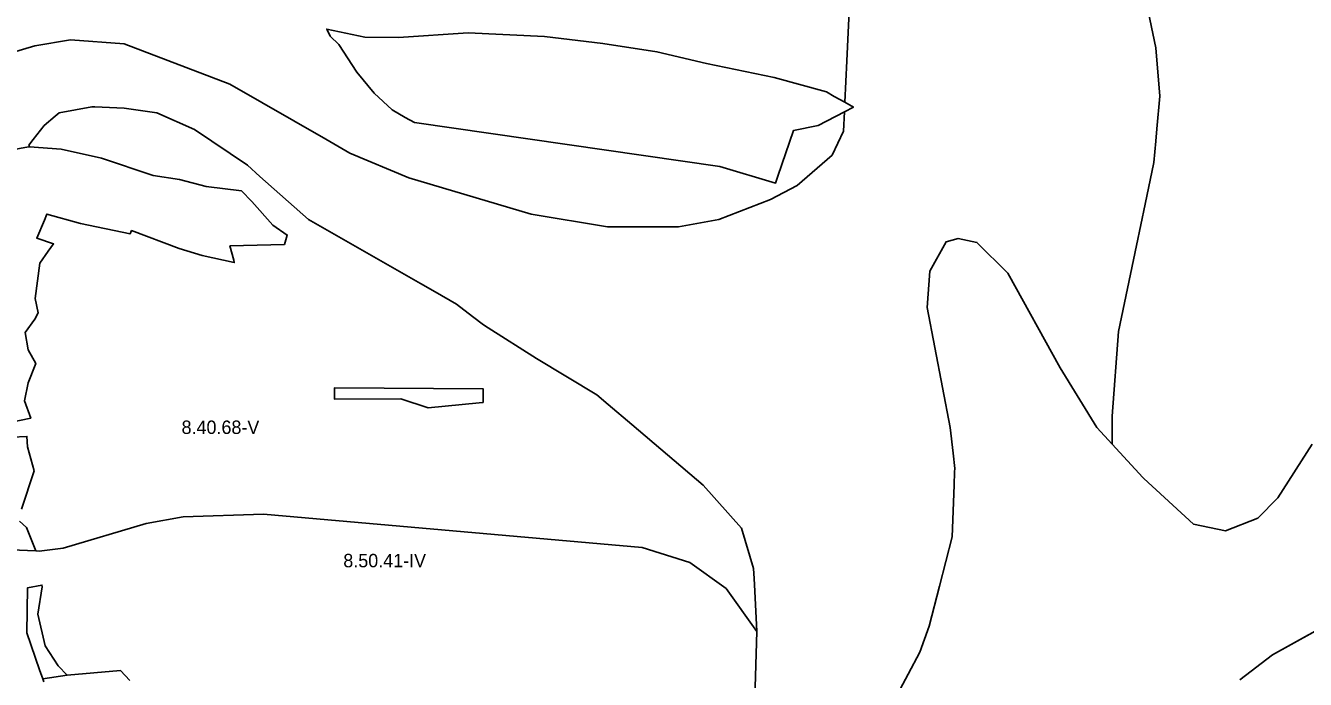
# Model space of a CAD drawing. Extents: x -547623 to -533936, y -1096714 to -1086523.
# Drawn here: x -543738 to -542784, y -1092854 to -1092367 of the extents above; entities that cross this region are included whole.
import ezdxf

# ---------------------------------------------------------------- set-up
doc = ezdxf.new("R2010")
doc.units = 0
doc.layers.add('Vrstva 27', color=7, linetype='Continuous')
doc.layers.add('Vrstva 28', color=7, linetype='Continuous')

msp = doc.modelspace()

# ---------------------------------------------------------------- linework, layer by layer
at = {"layer": 'Vrstva 28'}
for p, q in [((-542905, -1092338.5), (-542895.5, -1092383.5)), ((-542895.5, -1092383.5), (-542905, -1092338.5)), ((-543126.01, -1092393.13), (-543124, -1092351)), ((-543124, -1092351), (-543126.01, -1092393.13)), ((-543750, -1092387.4), (-543731.5, -1092382)), ((-543731.5, -1092382), (-543750, -1092387.4)), ((-543731.5, -1092382), (-543705, -1092377.5)), ((-543705, -1092377.5), (-543731.5, -1092382)), ((-543705, -1092377.5), (-543665, -1092380.5)), ((-543665, -1092380.5), (-543705, -1092377.5)), ((-543665, -1092380.5), (-543586, -1092410.5)), ((-543586, -1092410.5), (-543665, -1092380.5)), ((-542895.5, -1092383.5), (-542892.5, -1092419.5)), ((-542892.5, -1092419.5), (-542895.5, -1092383.5)), ((-543127.48, -1092424.11), (-543126.01, -1092393.13)), ((-543126.01, -1092393.13), (-543127.48, -1092424.11)), ((-543586, -1092410.5), (-543514.54, -1092451.62)), ((-543514.54, -1092451.62), (-543586, -1092410.5)), ((-542892.5, -1092419.5), (-542894.72, -1092443.92)), ((-542894.72, -1092443.92), (-542892.5, -1092419.5)), ((-543713.5, -1092432), (-543716.46, -1092434.56)), ((-543716.46, -1092434.56), (-543713.5, -1092432)), ((-543689, -1092427.5), (-543713.5, -1092432)), ((-543713.5, -1092432), (-543689, -1092427.5)), ((-543686.89, -1092427.59), (-543689, -1092427.5)), ((-543689, -1092427.5), (-543686.89, -1092427.59)), ((-543665, -1092428.5), (-543686.89, -1092427.59)), ((-543686.89, -1092427.59), (-543665, -1092428.5)), ((-543640.5, -1092432), (-543665, -1092428.5)), ((-543665, -1092428.5), (-543640.5, -1092432)), ((-543612.5, -1092444.5), (-543640.5, -1092432)), ((-543640.5, -1092432), (-543612.5, -1092444.5)), ((-543128.5, -1092445.5), (-543127.82, -1092431.2)), ((-543127.82, -1092431.2), (-543128.5, -1092445.5)), ((-543724.5, -1092441.5), (-543732.77, -1092451.93)), ((-543732.77, -1092451.93), (-543724.5, -1092441.5)), ((-543716.46, -1092434.56), (-543724.5, -1092441.5)), ((-543724.5, -1092441.5), (-543716.46, -1092434.56)), ((-543732.77, -1092451.93), (-543736, -1092456)), ((-543736, -1092456), (-543732.77, -1092451.93)), ((-543573, -1092471), (-543612.5, -1092444.5)), ((-543612.5, -1092444.5), (-543573, -1092471)), ((-543514.54, -1092451.62), (-543496.5, -1092462)), ((-543496.5, -1092462), (-543514.54, -1092451.62)), ((-543137, -1092463.5), (-543128.5, -1092445.5)), ((-543128.5, -1092445.5), (-543137, -1092463.5)), ((-542894.72, -1092443.92), (-542895.55, -1092453.01)), ((-542895.55, -1092453.01), (-542894.72, -1092443.92)), ((-543735.62, -1092457.42), (-543736, -1092456)), ((-543736, -1092456), (-543735.62, -1092457.42)), ((-542895.55, -1092453.01), (-542897, -1092469)), ((-542897, -1092469), (-542895.55, -1092453.01)), ((-543563.64, -1092479.33), (-543573, -1092471)), ((-543573, -1092471), (-543563.64, -1092479.33)), ((-543496.5, -1092462), (-543452.5, -1092480.5)), ((-543452.5, -1092480.5), (-543496.5, -1092462)), ((-543163, -1092486), (-543137, -1092463.5)), ((-543137, -1092463.5), (-543163, -1092486)), ((-542897, -1092469), (-542903.55, -1092500.13)), ((-542903.55, -1092500.13), (-542897, -1092469)), ((-543527.5, -1092511.5), (-543563.64, -1092479.33)), ((-543563.64, -1092479.33), (-543527.5, -1092511.5)), ((-543452.5, -1092480.5), (-543361.5, -1092507.5)), ((-543361.5, -1092507.5), (-543452.5, -1092480.5)), ((-543183, -1092496.5), (-543163, -1092486)), ((-543163, -1092486), (-543183, -1092496.5)), ((-543221.5, -1092511.5), (-543183, -1092496.5)), ((-543183, -1092496.5), (-543221.5, -1092511.5)), ((-543361.5, -1092507.5), (-543304.5, -1092517)), ((-543304.5, -1092517), (-543361.5, -1092507.5)), ((-542903.55, -1092500.13), (-542909.98, -1092530.74)), ((-542909.98, -1092530.74), (-542903.55, -1092500.13)), ((-543443.8, -1092559.22), (-543527.5, -1092511.5)), ((-543527.5, -1092511.5), (-543443.8, -1092559.22)), ((-543304.5, -1092517), (-543251.5, -1092517)), ((-543251.5, -1092517), (-543304.5, -1092517)), ((-543251.5, -1092517), (-543221.5, -1092511.5)), ((-543221.5, -1092511.5), (-543251.5, -1092517)), ((-543064, -1092550), (-543052, -1092528)), ((-543052, -1092528), (-543064, -1092550)), ((-543052, -1092528), (-543043, -1092525.5)), ((-543043, -1092525.5), (-543052, -1092528)), ((-543043, -1092525.5), (-543029, -1092528.5)), ((-543029, -1092528.5), (-543043, -1092525.5)), ((-543029, -1092528.5), (-543006, -1092551.5)), ((-543006, -1092551.5), (-543029, -1092528.5)), ((-542909.98, -1092530.74), (-542923.5, -1092595)), ((-542923.5, -1092595), (-542909.98, -1092530.74)), ((-543066, -1092577), (-543064, -1092550)), ((-543064, -1092550), (-543066, -1092577)), ((-543006, -1092551.5), (-542967, -1092622)), ((-542967, -1092622), (-543006, -1092551.5)), ((-543432.97, -1092565.39), (-543443.8, -1092559.22)), ((-543443.8, -1092559.22), (-543432.97, -1092565.39)), ((-543417, -1092574.5), (-543432.97, -1092565.39)), ((-543432.97, -1092565.39), (-543417, -1092574.5)), ((-543405.16, -1092583.68), (-543417, -1092574.5)), ((-543417, -1092574.5), (-543405.16, -1092583.68)), ((-543397, -1092590), (-543405.16, -1092583.68)), ((-543405.16, -1092583.68), (-543397, -1092590)), ((-543049, -1092666.5), (-543066, -1092577)), ((-543066, -1092577), (-543049, -1092666.5)), ((-543393.5, -1092592.22), (-543397, -1092590)), ((-543397, -1092590), (-543393.5, -1092592.22)), ((-543357.5, -1092615), (-543393.5, -1092592.22)), ((-543393.5, -1092592.22), (-543357.5, -1092615)), ((-542923.5, -1092595), (-542928, -1092658)), ((-542928, -1092658), (-542923.5, -1092595)), ((-543312.5, -1092642), (-543357.5, -1092615)), ((-543357.5, -1092615), (-543312.5, -1092642)), ((-542967, -1092622), (-542939.5, -1092666.5)), ((-542939.5, -1092666.5), (-542967, -1092622)), ((-543303.98, -1092649.23), (-543312.5, -1092642)), ((-543312.5, -1092642), (-543303.98, -1092649.23)), ((-543286.24, -1092664.3), (-543303.98, -1092649.23)), ((-543303.98, -1092649.23), (-543286.24, -1092664.3)), ((-542928, -1092658), (-542928, -1092678.99)), ((-542928, -1092678.99), (-542928, -1092658)), ((-543233, -1092709.5), (-543286.24, -1092664.3)), ((-543286.24, -1092664.3), (-543233, -1092709.5)), ((-543046.8, -1092685.64), (-543049, -1092666.5)), ((-543049, -1092666.5), (-543046.8, -1092685.64)), ((-542939.5, -1092666.5), (-542928, -1092678.99)), ((-542928, -1092678.99), (-542939.5, -1092666.5)), ((-542928, -1092678.99), (-542905.28, -1092703.66)), ((-542905.28, -1092703.66), (-542928, -1092678.99)), ((-542804.5, -1092719), (-542779, -1092679)), ((-542779, -1092679), (-542804.5, -1092719)), ((-543045.5, -1092697), (-543046.8, -1092685.64)), ((-543046.8, -1092685.64), (-543045.5, -1092697)), ((-543045.98, -1092709.37), (-543045.6, -1092699.45)), ((-543045.6, -1092699.45), (-543045.98, -1092709.37)), ((-543045.6, -1092699.45), (-543045.5, -1092697)), ((-543045.5, -1092697), (-543045.6, -1092699.45)), ((-543204.5, -1092741.5), (-543233, -1092709.5)), ((-543233, -1092709.5), (-543204.5, -1092741.5)), ((-543047.5, -1092748), (-543045.98, -1092709.37)), ((-543045.98, -1092709.37), (-543047.5, -1092748)), ((-542905.28, -1092703.66), (-542904.5, -1092704.5)), ((-542904.5, -1092704.5), (-542905.28, -1092703.66)), ((-542904.5, -1092704.5), (-542867.5, -1092738.5)), ((-542867.5, -1092738.5), (-542904.5, -1092704.5)), ((-542819.5, -1092734), (-542804.5, -1092719)), ((-542804.5, -1092719), (-542819.5, -1092734)), ((-543648.5, -1092738), (-543710.5, -1092756.5)), ((-543710.5, -1092756.5), (-543648.5, -1092738)), ((-543621, -1092733), (-543648.5, -1092738)), ((-543648.5, -1092738), (-543621, -1092733)), ((-543561, -1092731), (-543621, -1092733)), ((-543621, -1092733), (-543561, -1092731)), ((-543278.5, -1092756), (-543561, -1092731)), ((-543561, -1092731), (-543278.5, -1092756)), ((-542843.5, -1092743.5), (-542819.5, -1092734)), ((-542819.5, -1092734), (-542843.5, -1092743.5)), ((-543195.5, -1092771.5), (-543204.5, -1092741.5)), ((-543204.5, -1092741.5), (-543195.5, -1092771.5)), ((-542867.5, -1092738.5), (-542843.5, -1092743.5)), ((-542843.5, -1092743.5), (-542867.5, -1092738.5)), ((-543710.5, -1092756.5), (-543728.18, -1092758.57)), ((-543728.18, -1092758.57), (-543710.5, -1092756.5)), ((-543243, -1092767), (-543278.5, -1092756)), ((-543278.5, -1092756), (-543243, -1092767)), ((-543056.9, -1092784.78), (-543047.5, -1092748)), ((-543047.5, -1092748), (-543056.9, -1092784.78)), ((-543728.18, -1092758.57), (-543730.85, -1092758.45)), ((-543216, -1092786.5), (-543243, -1092767)), ((-543243, -1092767), (-543216, -1092786.5)), ((-543195.1, -1092778.98), (-543195.5, -1092771.5)), ((-543195.5, -1092771.5), (-543195.1, -1092778.98)), ((-542808.5, -1092836), (-542698, -1092774.5)), ((-542698, -1092774.5), (-542808.5, -1092836)), ((-543737, -1092786), (-543737.5, -1092819.5)), ((-543737.5, -1092819.5), (-543737, -1092786)), ((-543726.22, -1092783.93), (-543737, -1092786)), ((-543737, -1092786), (-543726.22, -1092783.93)), ((-543729.26, -1092805.54), (-543725.94, -1092785.28)), ((-543725.94, -1092785.28), (-543729.26, -1092805.54)), ((-543725.94, -1092785.28), (-543726.22, -1092783.93)), ((-543726.22, -1092783.93), (-543725.94, -1092785.28)), ((-543194.6, -1092788.49), (-543195.1, -1092778.98)), ((-543195.1, -1092778.98), (-543194.6, -1092788.49)), ((-543064.5, -1092814.5), (-543056.9, -1092784.78)), ((-543056.9, -1092784.78), (-543064.5, -1092814.5)), ((-543193, -1092818.5), (-543216, -1092786.5)), ((-543216, -1092786.5), (-543193, -1092818.5)), ((-543193, -1092818.5), (-543194.6, -1092788.49)), ((-543194.6, -1092788.49), (-543193, -1092818.5)), ((-543723.83, -1092829.26), (-543729.26, -1092805.54)), ((-543729.26, -1092805.54), (-543723.83, -1092829.26)), ((-543071.5, -1092834), (-543064.5, -1092814.5)), ((-543064.5, -1092814.5), (-543071.5, -1092834)), ((-543737.5, -1092819.5), (-543728, -1092847)), ((-543728, -1092847), (-543737.5, -1092819.5)), ((-543194.49, -1092868.4), (-543193, -1092818.5)), ((-543193, -1092818.5), (-543194.49, -1092868.4)), ((-543714.02, -1092843.99), (-543723.83, -1092829.26)), ((-543723.83, -1092829.26), (-543714.02, -1092843.99)), ((-543080.21, -1092850.2), (-543071.5, -1092834)), ((-543071.5, -1092834), (-543080.21, -1092850.2)), ((-542833, -1092854.5), (-542808.5, -1092836)), ((-542808.5, -1092836), (-542833, -1092854.5)), ((-543728, -1092847), (-543725.52, -1092853.86)), ((-543725.52, -1092853.86), (-543728, -1092847)), ((-543707.43, -1092850.98), (-543714.02, -1092843.99)), ((-543714.02, -1092843.99), (-543707.43, -1092850.98)), ((-543100, -1092887), (-543080.21, -1092850.2)), ((-543080.21, -1092850.2), (-543100, -1092887))]:
    msp.add_line(p, q, dxfattribs=at)
for points in [[(-543127.48, -1092424.11), (-543135.44, -1092419.71), (-543141.26, -1092416.35), (-543180.27, -1092405.55), (-543230.62, -1092395.31), (-543267.6, -1092386.42), (-543307.95, -1092380.25), (-543351.33, -1092375), (-543408.37, -1092372.43), (-543460.4, -1092375.8), (-543485.47, -1092375.46), (-543513.81, -1092369.5), (-543511.22, -1092374.73), (-543504.81, -1092381.08), (-543491.43, -1092401.7), (-543478.56, -1092417.23), (-543464.96, -1092429.63), (-543455.41, -1092435.55), (-543448.33, -1092439.06), (-543220.75, -1092471.95), (-543179.1, -1092484.32), (-543177.33, -1092479.08), (-543165.69, -1092445.08), (-543147.31, -1092441.47), (-543127.82, -1092431.2), (-543121.08, -1092427.65), (-543127.48, -1092424.11)], [(-543735.62, -1092457.42), (-543736.26, -1092457.38), (-543756.35, -1092461.06)], [(-543751.31, -1092662.9), (-543734.54, -1092659.62), (-543739.14, -1092646.56), (-543736.53, -1092633.08), (-543730.86, -1092618.88), (-543736.38, -1092608.66), (-543738.83, -1092595.74), (-543731.63, -1092585.8), (-543729.02, -1092580.98), (-543731.17, -1092570.31), (-543727.92, -1092543.9), (-543721.47, -1092535.1), (-543717.52, -1092529.66), (-543730.09, -1092525.34), (-543724.39, -1092511.97), (-543722.64, -1092507.43), (-543697.41, -1092514.51), (-543660.49, -1092522.2), (-543659.4, -1092519.77), (-543623.94, -1092533.02), (-543606.77, -1092538.33), (-543582.79, -1092543.52), (-543583.21, -1092541.88), (-543586.02, -1092530.97), (-543545.38, -1092529.97), (-543543.25, -1092523.07), (-543554.01, -1092515.72), (-543569.73, -1092498.01), (-543577.51, -1092490.02), (-543603.64, -1092486.76), (-543623.75, -1092481.71), (-543643.31, -1092478.62), (-543681.93, -1092465.69), (-543711.9, -1092459.05), (-543735.62, -1092457.42), (-543735.62, -1092457.42), (-543735.62, -1092457.42)], [(-542779, -1092679), (-542804.5, -1092719), (-542819.5, -1092734), (-542843.5, -1092743.5), (-542867.5, -1092738.5), (-542904.5, -1092704.5), (-542905.28, -1092703.66), (-542928, -1092678.99), (-542939.5, -1092666.5), (-542967, -1092622), (-543006, -1092551.5), (-543029, -1092528.5), (-543043, -1092525.5), (-543052, -1092528), (-543064, -1092550), (-543066, -1092577), (-543049, -1092666.5), (-543046.8, -1092685.64), (-543045.5, -1092697), (-543045.6, -1092699.45), (-543045.98, -1092709.37), (-543047.5, -1092748), (-543056.9, -1092784.78), (-543064.5, -1092814.5), (-543071.5, -1092834), (-543080.21, -1092850.2), (-543100, -1092887)], [(-543438.14, -1092651.75), (-543400.13, -1092648.1), (-543397.29, -1092647.83), (-543397.17, -1092637.66), (-543507.94, -1092636.84), (-543508.02, -1092645.37), (-543458.66, -1092645.21), (-543438.14, -1092651.75)], [(-543741.42, -1092727.31), (-543731.94, -1092698.78), (-543737, -1092680.86), (-543737.44, -1092673.13), (-543748.77, -1092673.75)], [(-543749.08, -1092757.6), (-543730.85, -1092758.45), (-543737.84, -1092740.87), (-543743.08, -1092736.25)], [(-542833, -1092854.5), (-542808.5, -1092836), (-542698, -1092774.5)], [(-543707.43, -1092850.98), (-543714.02, -1092843.99), (-543723.83, -1092829.26), (-543729.26, -1092805.54), (-543725.94, -1092785.28), (-543726.22, -1092783.93), (-543737, -1092786), (-543737.5, -1092819.5), (-543728, -1092847), (-543725.52, -1092853.86)], [(-543660.75, -1092854.95), (-543667.66, -1092847.48), (-543707.43, -1092850.98), (-543725.53, -1092853.86), (-543724.81, -1092856.1)], [(-543725.52, -1092853.86), (-543707.43, -1092850.98)]]:
    msp.add_lwpolyline(points, dxfattribs=at)

# ---------------------------------------------------------------- texts
at = {"layer": 'Vrstva 27'}
for s, p in [('8.40.68-V', (-543622.1, -1092671.28)), ('8.50.41-IV', (-543501.48, -1092770.64))]:
    msp.add_text(s, height=10, dxfattribs=at).set_placement(p)

doc.saveas('drawing.dxf')
